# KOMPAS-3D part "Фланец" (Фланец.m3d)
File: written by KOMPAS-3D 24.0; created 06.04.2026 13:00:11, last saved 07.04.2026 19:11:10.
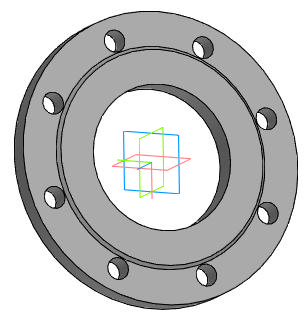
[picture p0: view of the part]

Document properties: Автор: R2D2; Полное имя файла: E:\Работа\Зайцев\Солянка\VSR1-13V-PED-F Клапан запорно-регулирующий DN.ru\DN125\исходные материалы\Фланец.m3d

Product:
- Component [standard]: (unnamed)  | qty 1  | Материал: ВЧ40 ГОСТ 7293-85 (density 7200 kg/m3); Масса: 6.38; additional columns: 125-16-01-2-B-ВЧ40-II-dв 141,5; Фланец; ГОСТ 33259-2015
- Part/product: Фланец
    Масса: 5.514788

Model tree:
1. Эскиз:8
2. Элемент выдавливания:8
     Расстояние 2 = 22
3. Эскиз:10  (with: Грань.Элемент выдавливания:8, Ребро.Элемент выдавливания:8)
4. Элемент выдавливания:12
5. Массив по концентрической сетке:1  (with: Элемент выдавливания:12, Эскиз:10)  (8 pattern instances)
     Шаг 2 = 360

Expressions: v520+50
Referenced files in C:\Program Files\ASCON\KOMPAS-3D v24\Libs\PolynomLib\DATA\vault\Methods\Kompas\3D\: PLib_Flange_GOST_33259_1401.m3d
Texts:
  BOSimple***Material:38d6725a-5efe-48e1-b177-a7817acb862a
  BOSimple***PART:9e2a88ff-ace4-5574-87c6-91ed90a4d33c***SHORTLOC:B6A6_23E38AE8DB154823[II;2;Круглый;125;16;141,5;0;ВЧ40 ГОСТ 7293-85]
  Ch34
  Плоскость XY.Начало координат
  Ось Z.Начало координат
  Plane ZX. Origin
  Плоскость ZX.Начало координат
